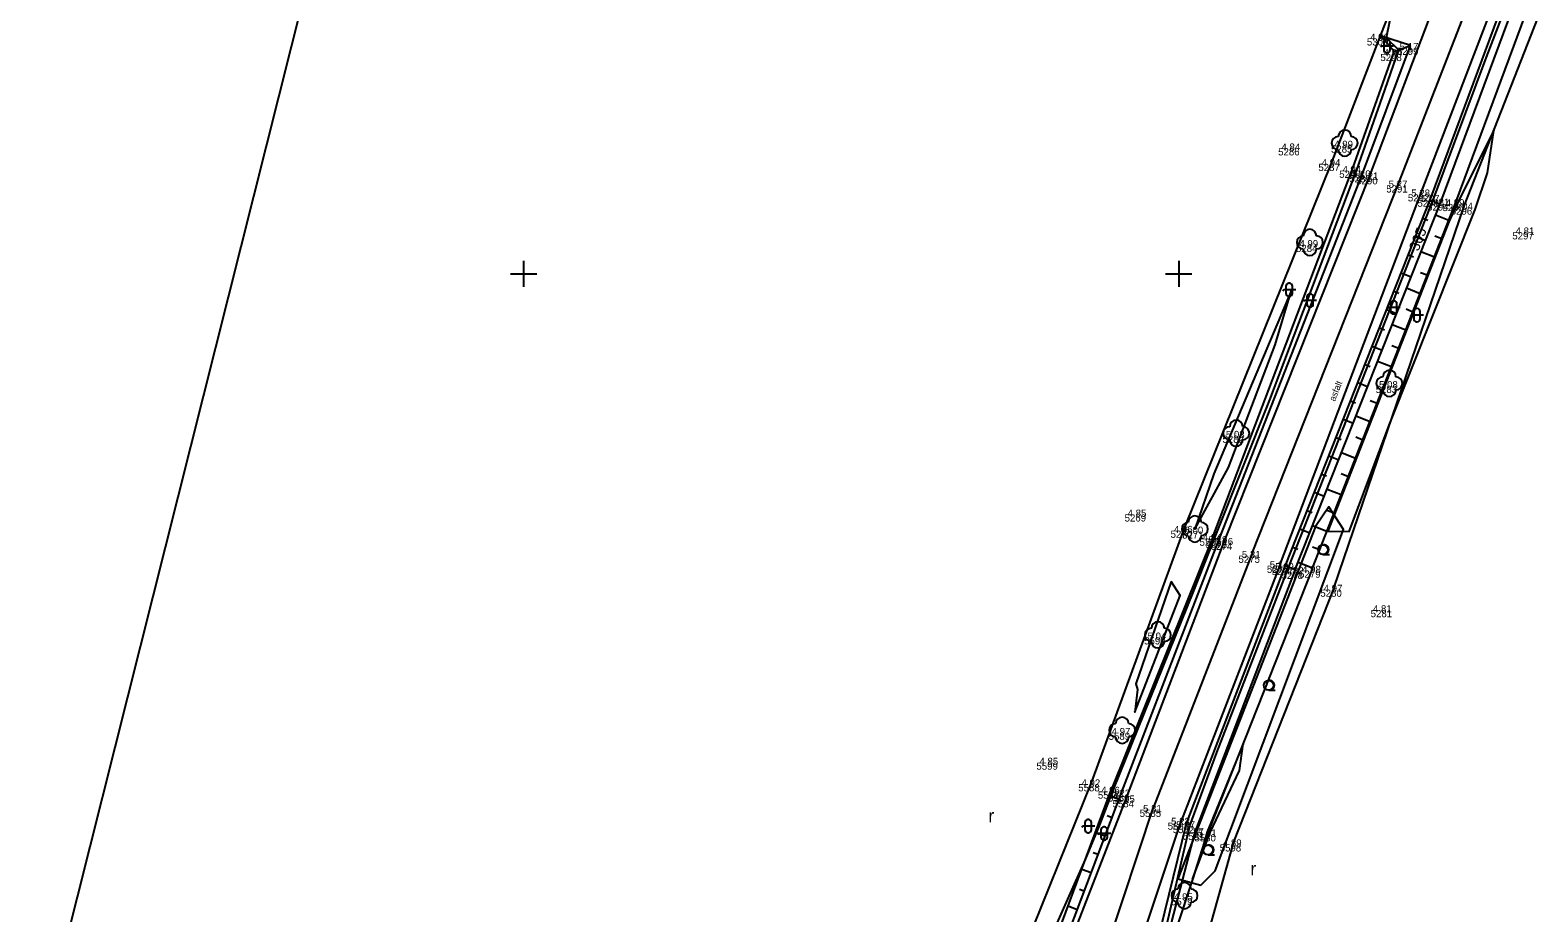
# Model space of a CAD drawing. Extents: x -740053 to -737517, y -1033516 to -1032488.
# Drawn here: x -739137.7 to -739022.6, y -1033398.8 to -1033331.4 of the extents above; entities that cross this region are included whole.
import ezdxf

# ---------------------------------------------------------------- set-up
doc = ezdxf.new("R2010")
doc.units = 0
for name, color, linetype in [('bod-cislo', 7, 'Continuous'), ('bod-oznac', 7, 'Continuous'), ('bod-vyska', 7, 'Continuous'), ('bod-vyska100', 7, 'Continuous'), ('Contours highlighted', 7, 'Continuous'), ('Contours text', 7, 'Continuous'), ('ctv-sit', 7, 'Continuous'), ('Hranice-zelene', 7, 'Continuous'), ('nazvy-bud-povr', 7, 'Continuous'), ('osa-komunikace', 7, 'Continuous'), ('Predmety bez rozlišeni', 7, 'Continuous'), ('rozhraní kultůr', 7, 'Continuous'), ('silnice', 7, 'Continuous'), ('Technické šrafy', 7, 'Continuous'), ('Terenni-hrana', 7, 'Continuous'), ('Znacky-kultury', 7, 'Continuous')]:
    doc.layers.add(name, color=color, linetype=linetype)

# ---------------------------------------------------------------- blocks, each defined once
blk = doc.blocks.new('POINT_DISPLAY')
blk.add_line((0, 0), (0, 0))
blk = doc.blocks.new('p_strom')
for centre, start, end in [((-1, 0), 90, 270), ((0, 1), 0, 180), ((1, 0), 270, 90), ((0, -1), 180, 0)]:
    blk.add_arc(centre, 1, start, end)
at = {"rotation": -180}
blk.add_blockref('POINT_DISPLAY', (0, 0), dxfattribs=at)
blk = doc.blocks.new('p_orna')
blk.add_text('r', height=2).set_placement((0, 0))
blk = doc.blocks.new('p_neplod')
for p, q in [((-0.82, 0), (-0.99, -0.18)), ((1, 0), (-0.82, 0)), ((-0.49, 0.56), (-0.49, -0.55)), ((0.05, 1.01), (-0.04, 1.01)), ((0.5, -0.55), (0.5, 0.56)), ((-0.04, -1), (0.05, -1))]:
    blk.add_line(p, q)
for centre, start, end in [((-0.04, 0.56), 90, 180), ((0.05, 0.56), 0, 90), ((-0.04, -0.55), 180, 270), ((0.05, -0.55), 270, 0)]:
    blk.add_arc(centre, 0.45, start, end)
blk = doc.blocks.new('p_leskro')
blk.add_line((0, -0.75), (1, -0.75))
blk.add_circle((0, 0), 0.75)
blk.add_arc((0.13, 0), 0.75, 264.8832, 95.1168)
blk = doc.blocks.new('ctvsit')
for p, q in [((2, 0), (-2, 0)), ((0, -2), (0, 2))]:
    blk.add_line(p, q)

msp = doc.modelspace()

# ---------------------------------------------------------------- linework, layer by layer
at = {"layer": 'Contours highlighted'}
for points in [[(-739033.63, -1033329.37), (-739034.16, -1033331.98), (-739033.23, -1033332.91), (-739034.46, -1033336.5), (-739036.42, -1033342.07), (-739043.08, -1033359.62), (-739047.24, -1033370.07), (-739048.86, -1033374.2), (-739055, -1033389.35), (-739056.04, -1033392.04), (-739057.13, -1033394.7), (-739062.85, -1033407.5), (-739063.4, -1033409.17), (-739067.01, -1033417.01), (-739067.91, -1033419.05), (-739069.14, -1033421.5), (-739069.97, -1033423.2)], [(-739041.51, -1033430.37), (-739042.92, -1033427.76), (-739040.25, -1033429.35), (-739038.31, -1033430.14), (-739041.49, -1033426.92), (-739048.38, -1033420.37), (-739048.92, -1033419.44), (-739050.89, -1033416.59), (-739051.32, -1033415.51), (-739052.12, -1033413.44), (-739052.21, -1033410.39), (-739052.59, -1033407.08), (-739051.58, -1033402.52), (-739049.16, -1033392.13), (-739047.08, -1033386.52), (-739041.6, -1033372.35), (-739033.63, -1033352.1), (-739030.53, -1033344.23), (-739026.52, -1033333.46), (-739024.99, -1033329.5)], [(-739025.95, -1033339.05), (-739028.69, -1033344.53), (-739029.39, -1033346.02), (-739038.61, -1033369.64), (-739036.99, -1033369.67), (-739033.88, -1033361.41), (-739027.37, -1033345.08), (-739026.43, -1033342.28), (-739025.95, -1033339.05)], [(-739041.4, -1033351.24), (-739047.31, -1033365.27), (-739048.77, -1033369.47), (-739046.19, -1033364.78), (-739042.64, -1033355.42), (-739041.4, -1033351.24)], [(-739050.58, -1033373.48), (-739053.27, -1033381.29), (-739053.15, -1033381.71), (-739053.35, -1033383.44), (-739049.9, -1033374.54), (-739050.58, -1033373.48)], [(-739045.09, -1033385.87), (-739047.4, -1033391.53), (-739047.82, -1033392.57), (-739048.05, -1033393.39), (-739048.94, -1033396.2), (-739047.59, -1033392.64), (-739045.35, -1033387.91), (-739045.09, -1033385.87)]]:
    msp.add_lwpolyline(points, dxfattribs=at)
at = {"layer": 'Hranice-zelene'}
msp.add_lwpolyline([(-739050.08, -1033396.17), (-739048.3, -1033396.66), (-739047.23, -1033395.55), (-739037.42, -1033369.51), (-739038.55, -1033367.78), (-739039.57, -1033369.27), (-739050.08, -1033396.17)], dxfattribs=at)
at = {"layer": 'osa-komunikace'}
for p, q in [((-739033.19, -1033343.06), (-739027.55, -1033328.5)), ((-739044.39, -1033371.32), (-739033.19, -1033343.06)), ((-739044.39, -1033371.32), (-739051.93, -1033390.71)), ((-739056.28, -1033403.86), (-739051.93, -1033390.71))]:
    msp.add_line(p, q, dxfattribs=at)
at = {"layer": 'Predmety bez rozlišeni'}
msp.add_line((-739137.66, -1033411.85), (-739112.03, -1033310.03), dxfattribs=at)
at = {"layer": 'rozhraní kultůr'}
for p, q in [((-739028.19, -1033344.75), (-739022.59, -1033330.49)), ((-739038.14, -1033373.91), (-739028.19, -1033344.75)), ((-739038.14, -1033373.91), (-739045.82, -1033393.35)), ((-739045.82, -1033393.35), (-739051.33, -1033413.18))]:
    msp.add_line(p, q, dxfattribs=at)
at = {"layer": 'silnice'}
for p, q in [((-739035.4, -1033342.44), (-739029.79, -1033327.65)), ((-739031.46, -1033343.74), (-739025.89, -1033329.21)), ((-739046.49, -1033370.33), (-739035.4, -1033342.44)), ((-739042.22, -1033372.09), (-739031.46, -1033343.74)), ((-739053.99, -1033389.98), (-739046.49, -1033370.33)), ((-739042.22, -1033372.09), (-739049.79, -1033391.69)), ((-739060.96, -1033407.9), (-739053.99, -1033389.98)), ((-739053.39, -1033402.5), (-739049.79, -1033391.69))]:
    msp.add_line(p, q, dxfattribs=at)
at = {"layer": 'Technické šrafy'}
for p, q in [((-739030.81, -1033344.35), (-739030.06, -1033344.65)), ((-739031.36, -1033345.75), (-739030.99, -1033345.9)), ((-739029.39, -1033345.92), (-739030.41, -1033345.52)), ((-739031.91, -1033347.14), (-739031.17, -1033347.44)), ((-739029.93, -1033347.32), (-739030.45, -1033347.12)), ((-739032.47, -1033348.54), (-739032.09, -1033348.69)), ((-739030.48, -1033348.72), (-739031.51, -1033348.31)), ((-739033.02, -1033349.93), (-739032.27, -1033350.23)), ((-739031.03, -1033350.11), (-739031.55, -1033349.91)), ((-739033.57, -1033351.33), (-739033.2, -1033351.48)), ((-739031.57, -1033351.51), (-739032.62, -1033351.1)), ((-739034.12, -1033352.72), (-739033.37, -1033353.02)), ((-739032.12, -1033352.91), (-739032.64, -1033352.7)), ((-739032.67, -1033354.3), (-739033.72, -1033353.89)), ((-739034.67, -1033354.12), (-739034.3, -1033354.27)), ((-739035.23, -1033355.51), (-739034.48, -1033355.81)), ((-739033.21, -1033355.7), (-739033.74, -1033355.49)), ((-739035.78, -1033356.91), (-739035.4, -1033357.06)), ((-739033.76, -1033357.1), (-739034.82, -1033356.68)), ((-739036.33, -1033358.3), (-739035.58, -1033358.6)), ((-739036.88, -1033359.7), (-739036.51, -1033359.85)), ((-739034.86, -1033359.89), (-739035.39, -1033359.68)), ((-739037.43, -1033361.09), (-739036.68, -1033361.39)), ((-739035.4, -1033361.29), (-739036.48, -1033360.87)), ((-739037.99, -1033362.49), (-739037.61, -1033362.64)), ((-739035.95, -1033362.68), (-739036.49, -1033362.47)), ((-739038.54, -1033363.88), (-739037.79, -1033364.18)), ((-739036.5, -1033364.08), (-739037.58, -1033363.66)), ((-739039.09, -1033365.28), (-739038.72, -1033365.42)), ((-739037.04, -1033365.48), (-739037.59, -1033365.26)), ((-739037.59, -1033366.87), (-739038.68, -1033366.45)), ((-739039.64, -1033366.67), (-739038.89, -1033366.97)), ((-739040.19, -1033368.07), (-739039.82, -1033368.21)), ((-739038.14, -1033368.27), (-739038.69, -1033368.05)), ((-739040.75, -1033369.46), (-739040, -1033369.76)), ((-739038.69, -1033369.67), (-739039.79, -1033369.23)), ((-739041.3, -1033370.86), (-739040.92, -1033371)), ((-739039.23, -1033371.06), (-739039.79, -1033370.85)), ((-739041.85, -1033372.25), (-739041.1, -1033372.55)), ((-739039.78, -1033372.46), (-739040.89, -1033372.02)), ((-739054.56, -1033390.11), (-739055.31, -1033389.83)), ((-739055.09, -1033391.51), (-739055.46, -1033391.37)), ((-739055.63, -1033392.91), (-739056.36, -1033392.64)), ((-739056.16, -1033394.32), (-739056.52, -1033394.18)), ((-739056.69, -1033395.72), (-739057.4, -1033395.45)), ((-739057.22, -1033397.12), (-739057.57, -1033396.99)), ((-739057.75, -1033398.53), (-739058.45, -1033398.26))]:
    msp.add_line(p, q, dxfattribs=at)
at = {"layer": 'Terenni-hrana'}
for p, q in [((-739034.59, -1033331.84), (-739032.67, -1033326.89)), ((-739030.73, -1033344.15), (-739025.25, -1033329.41)), ((-739029.98, -1033344.44), (-739024.47, -1033329.67)), ((-739028.82, -1033344.48), (-739023.5, -1033330.16)), ((-739038.29, -1033341.42), (-739034.59, -1033331.84)), ((-739033.56, -1033333.03), (-739034.59, -1033331.84)), ((-739032.31, -1033332.56), (-739034.59, -1033331.84)), ((-739036.7, -1033341.94), (-739033.56, -1033333.03)), ((-739035.95, -1033342.28), (-739032.31, -1033332.56)), ((-739033.56, -1033333.03), (-739032.31, -1033332.56)), ((-739049.57, -1033369.41), (-739038.29, -1033341.42)), ((-739047.36, -1033370.02), (-739036.7, -1033341.94)), ((-739046.9, -1033370.2), (-739035.95, -1033342.28)), ((-739041.85, -1033372.25), (-739030.73, -1033344.15)), ((-739041.1, -1033372.55), (-739029.98, -1033344.44)), ((-739039.78, -1033372.46), (-739028.82, -1033344.48)), ((-739056.62, -1033388.76), (-739049.57, -1033369.41)), ((-739047.36, -1033370.02), (-739055.12, -1033389.32)), ((-739054.35, -1033389.54), (-739046.9, -1033370.2)), ((-739049.4, -1033391.95), (-739041.85, -1033372.25)), ((-739041.1, -1033372.55), (-739048.71, -1033392.47)), ((-739039.78, -1033372.46), (-739047.75, -1033392.58)), ((-739064.64, -1033408.62), (-739056.62, -1033388.76)), ((-739062.64, -1033409.51), (-739055.12, -1033389.32)), ((-739061.99, -1033409.75), (-739054.35, -1033389.54)), ((-739053.18, -1033407.3), (-739049.4, -1033391.95)), ((-739052.51, -1033407.05), (-739048.71, -1033392.47)), ((-739047.75, -1033392.58), (-739052.51, -1033407.05))]:
    msp.add_line(p, q, dxfattribs=at)

# ---------------------------------------------------------------- block references
at = {"layer": 'bod-oznac'}
for p in [(-739034.59, -1033331.84), (-739033.56, -1033333.03), (-739032.31, -1033332.56), (-739037.33, -1033340.02), (-739041.36, -1033340.23), (-739038.29, -1033341.42), (-739036.7, -1033341.94), (-739035.95, -1033342.28), (-739035.4, -1033342.44), (-739033.19, -1033343.06), (-739031.46, -1033343.74), (-739030.73, -1033344.15), (-739029.98, -1033344.44), (-739028.82, -1033344.48), (-739028.19, -1033344.75), (-739023.49, -1033346.64), (-739039.99, -1033347.6), (-739033.92, -1033358.36), (-739045.61, -1033362.16), (-739053.1, -1033368.17), (-739049.57, -1033369.41), (-739048.77, -1033369.47), (-739047.36, -1033370.02), (-739046.9, -1033370.2), (-739046.49, -1033370.33), (-739044.39, -1033371.32), (-739042.22, -1033372.09), (-739041.85, -1033372.25), (-739041.1, -1033372.55), (-739039.78, -1033372.46), (-739038.14, -1033373.91), (-739034.38, -1033375.47), (-739051.59, -1033377.55), (-739054.32, -1033384.83), (-739059.83, -1033387.11), (-739056.62, -1033388.76), (-739055.12, -1033389.32), (-739054.35, -1033389.54), (-739053.99, -1033389.98), (-739051.93, -1033390.71), (-739049.79, -1033391.69), (-739049.4, -1033391.95), (-739048.71, -1033392.47), (-739047.75, -1033392.58), (-739045.82, -1033393.35), (-739049.56, -1033397.45)]:
    msp.add_blockref('POINT_DISPLAY', p, dxfattribs=at)
at = {"layer": 'ctv-sit', "xscale": 0.5, "yscale": 0.5, "rotation": 180}
for p in [(-739100, -1033350), (-739050, -1033350)]:
    msp.add_blockref('ctvsit', p, dxfattribs=at)
at = {"layer": 'Znacky-kultury', "xscale": 0.5, "yscale": 0.5}
for name, p in [('p_neplod', (-739034.11, -1033332.62)), ('p_strom', (-739037.33, -1033340.02)), ('p_strom', (-739039.99, -1033347.6)), ('p_neplod', (-739041.57, -1033351.22)), ('p_neplod', (-739039.98, -1033352.03)), ('p_neplod', (-739033.59, -1033352.56)), ('p_neplod', (-739031.82, -1033353.15)), ('p_strom', (-739033.92, -1033358.36)), ('p_strom', (-739045.61, -1033362.16)), ('p_strom', (-739048.77, -1033369.47)), ('p_leskro', (-739038.99, -1033371.04)), ('p_strom', (-739051.59, -1033377.55)), ('p_leskro', (-739043.13, -1033381.4)), ('p_strom', (-739054.32, -1033384.83)), ('p_orna', (-739064.53, -1033391.85)), ('p_neplod', (-739056.91, -1033392.15)), ('p_neplod', (-739055.69, -1033392.71)), ('p_leskro', (-739047.76, -1033393.96)), ('p_orna', (-739044.53, -1033395.89)), ('p_strom', (-739049.56, -1033397.45))]:
    msp.add_blockref(name, p, dxfattribs=at)

# ---------------------------------------------------------------- texts
at = {"layer": 'bod-cislo'}
for s, p in [('5300', (-739035.64, -1033332.57)), ('5299', (-739033.34, -1033333.29)), ('5298', (-739034.61, -1033333.76)), ('5286', (-739042.41, -1033340.96)), ('5285', (-739038.38, -1033340.75)), ('5287', (-739039.34, -1033342.15)), ('5288', (-739037.75, -1033342.67)), ('5289', (-739036.98, -1033343.01)), ('5290', (-739036.45, -1033343.17)), ('5291', (-739034.16, -1033343.79)), ('5292', (-739032.51, -1033344.47)), ('5293', (-739031.78, -1033344.88)), ('5294', (-739031.04, -1033345.17)), ('5295', (-739029.87, -1033345.21)), ('5296', (-739029.24, -1033345.48)), ('5297', (-739024.54, -1033347.37)), ('5284', (-739041.05, -1033348.33)), ('5283', (-739034.97, -1033359.09)), ('5282', (-739046.66, -1033362.89)), ('5269', (-739054.13, -1033368.9)), ('5270', (-739050.62, -1033370.14)), ('5271', (-739049.74, -1033370.2)), ('5272', (-739048.41, -1033370.75)), ('5273', (-739047.95, -1033370.93)), ('5274', (-739047.55, -1033371.06)), ('5275', (-739045.44, -1033372.05)), ('5276', (-739043.27, -1033372.82)), ('5277', (-739042.9, -1033372.98)), ('5278', (-739042.15, -1033373.28)), ('5279', (-739040.81, -1033373.19)), ('5280', (-739039.19, -1033374.64)), ('5281', (-739035.35, -1033376.2)), ('5590', (-739052.64, -1033378.28)), ('5589', (-739055.35, -1033385.56)), ('5599', (-739060.86, -1033387.84)), ('5588', (-739057.67, -1033389.49)), ('5587', (-739056.17, -1033390.05)), ('5586', (-739055.4, -1033390.27)), ('5584', (-739055.05, -1033390.71)), ('5585', (-739052.98, -1033391.44)), ('5583', (-739050.84, -1033392.42)), ('5582', (-739050.45, -1033392.68)), ('5581', (-739049.68, -1033393.2)), ('5580', (-739048.8, -1033393.31)), ('5598', (-739046.87, -1033394.08)), ('5579', (-739050.59, -1033398.18))]:
    msp.add_text(s, height=0.55, dxfattribs=at).set_placement(p)
at = {"layer": 'bod-vyska'}
for s, p in [('4 96', (-739035.39, -1033332.21)), ('4 94', (-739034.36, -1033333.4)), ('5 17', (-739033.14, -1033332.93)), ('4 84', (-739042.16, -1033340.6)), ('4 99', (-739038.13, -1033340.39)), ('4 94', (-739039.09, -1033341.79)), ('4 94', (-739037.5, -1033342.31)), ('5 10', (-739036.78, -1033342.65)), ('5 21', (-739036.19, -1033342.81)), ('5 27', (-739033.98, -1033343.43)), ('5 28', (-739032.25, -1033344.11)), ('5 07', (-739031.52, -1033344.52)), ('4 81', (-739030.78, -1033344.81)), ('4 99', (-739029.62, -1033344.85)), ('5 04', (-739028.98, -1033345.12)), ('4 81', (-739024.29, -1033347.01)), ('4 99', (-739040.79, -1033347.97)), ('5 08', (-739034.71, -1033358.73)), ('5 03', (-739046.4, -1033362.53)), ('4 85', (-739053.9, -1033368.54)), ('4 96', (-739050.37, -1033369.78)), ('5 00', (-739049.56, -1033369.84)), ('4 94', (-739048.16, -1033370.39)), ('5 18', (-739047.73, -1033370.57)), ('5 26', (-739047.28, -1033370.7)), ('5 31', (-739045.18, -1033371.69)), ('5 14', (-739043.05, -1033372.46)), ('5 09', (-739042.64, -1033372.62)), ('4 98', (-739040.58, -1033372.83)), ('4 82', (-739041.9, -1033372.92)), ('4 97', (-739038.94, -1033374.28)), ('4 81', (-739035.18, -1033375.84)), ('5 04', (-739052.38, -1033377.92)), ('4 97', (-739055.12, -1033385.2)), ('4 85', (-739060.63, -1033387.48)), ('4 92', (-739057.42, -1033389.13)), ('4 96', (-739055.92, -1033389.69)), ('5 22', (-739055.14, -1033389.91)), ('5 25', (-739054.78, -1033390.35)), ('5 31', (-739052.72, -1033391.08)), ('5 23', (-739050.58, -1033392.06)), ('5 07', (-739050.19, -1033392.32)), ('4 87', (-739049.51, -1033392.84)), ('5 01', (-739048.54, -1033392.95)), ('4 89', (-739046.63, -1033393.71)), ('4 95', (-739050.36, -1033397.82))]:
    msp.add_text(s, height=0.55, dxfattribs=at).set_placement(p)
at = {"layer": 'bod-vyska100'}
for s, p in [('304 96', (-739034.76, -1033331.87)), ('304 94', (-739033.73, -1033333.06)), ('305 17', (-739032.48, -1033332.59)), ('304 99', (-739037.5, -1033340.05)), ('304 84', (-739041.53, -1033340.26)), ('304 94', (-739038.46, -1033341.45)), ('304 94', (-739036.87, -1033341.97)), ('305 10', (-739036.12, -1033342.31)), ('305 21', (-739035.57, -1033342.47)), ('305 27', (-739033.36, -1033343.09)), ('305 28', (-739031.63, -1033343.77)), ('305 07', (-739030.9, -1033344.18)), ('304 81', (-739030.15, -1033344.47)), ('304 99', (-739028.99, -1033344.51)), ('305 04', (-739028.36, -1033344.78)), ('304 81', (-739023.66, -1033346.67)), ('304 99', (-739040.16, -1033347.63)), ('305 08', (-739034.09, -1033358.39)), ('305 03', (-739045.78, -1033362.19)), ('304 85', (-739053.27, -1033368.2)), ('304 96', (-739049.74, -1033369.44)), ('305 00', (-739048.94, -1033369.5)), ('304 94', (-739047.53, -1033370.05)), ('305 18', (-739047.07, -1033370.23)), ('305 26', (-739046.66, -1033370.36)), ('305 31', (-739044.56, -1033371.35)), ('305 14', (-739042.39, -1033372.12)), ('305 09', (-739042.02, -1033372.28)), ('304 82', (-739041.27, -1033372.58)), ('304 98', (-739039.95, -1033372.49)), ('304 97', (-739038.31, -1033373.94)), ('304 81', (-739034.55, -1033375.5)), ('305 04', (-739051.76, -1033377.58)), ('304 97', (-739054.49, -1033384.86)), ('304 85', (-739060, -1033387.14)), ('304 92', (-739056.79, -1033388.79)), ('304 96', (-739055.29, -1033389.35)), ('305 22', (-739054.52, -1033389.57)), ('305 25', (-739054.16, -1033390.01)), ('305 31', (-739052.1, -1033390.74)), ('305 23', (-739049.96, -1033391.72)), ('305 07', (-739049.57, -1033391.98)), ('304 87', (-739048.88, -1033392.5)), ('305 01', (-739047.92, -1033392.61)), ('304 89', (-739045.99, -1033393.38)), ('304 95', (-739049.73, -1033397.48))]:
    msp.add_text(s, height=0.05, dxfattribs=at).set_placement(p)
at = {"layer": 'Contours text'}
msp.add_text('305', height=0.8, rotation=68.4754, dxfattribs=at).set_placement((-739031.71, -1033348.32))
at = {"layer": 'nazvy-bud-povr'}
msp.add_text('asfalt', height=0.5, rotation=68.5669, dxfattribs=at).set_placement((-739038.08, -1033359.77))

doc.saveas('drawing.dxf')
